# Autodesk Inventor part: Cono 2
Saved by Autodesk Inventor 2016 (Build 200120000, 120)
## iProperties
Created: 2017-06
Part Number: Cono 2
Material: Generic
Document SubType Name: Modeling
Designer: Administrator
Appearance: Generic
Author: Administrator
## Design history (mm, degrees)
feature "Body1"
body "Solid1"
